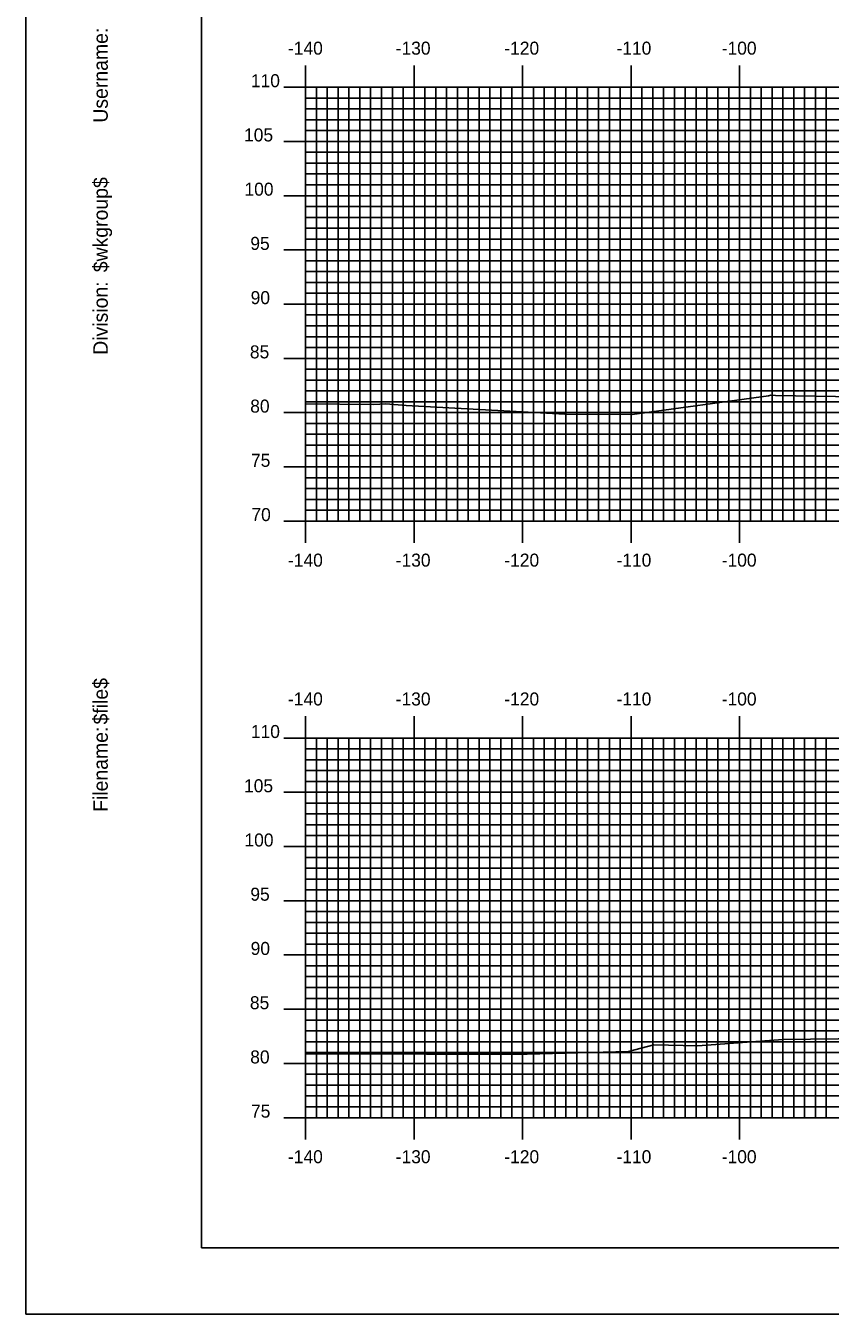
# Model space of a CAD drawing. Extents: x 852542 to 852886, y 364366 to 364586.
# Drawn here: x 852542.4 to 852616.5, y 364365.7 to 364484.5 of the extents above; entities that cross this region are included whole.
import ezdxf

# ---------------------------------------------------------------- set-up
doc = ezdxf.new("R2010")
doc.units = 0
for name, color, linetype in [('BORDER', 7, 'Continuous'), ('H_V ANNOTATION', 7, 'Continuous'), ('MAJOR', 7, 'Continuous'), ('MINOR', 7, 'Continuous'), ('PLOT BOUNDARY', 7, 'Continuous'), ('S_Roadway_Centerline', 7, 'Continuous')]:
    doc.layers.add(name, color=color, linetype=linetype)

msp = doc.modelspace()

# ---------------------------------------------------------------- linework, layer by layer
at = {"layer": 'BORDER'}
msp.add_lwpolyline([(852558.58, 364371.79), (852878.58, 364371.79), (852878.58, 364581.79), (852558.58, 364581.79)], close=True, dxfattribs=at)
at = {"layer": 'MAJOR'}
for p, q in [((852568.18, 364480.79), (852568.18, 364478.79)), ((852578.18, 364480.79), (852578.18, 364478.79)), ((852588.18, 364480.79), (852588.18, 364478.79)), ((852598.18, 364480.79), (852598.18, 364478.79)), ((852608.18, 364480.79), (852608.18, 364478.79)), ((852566.17, 364478.79), (852568.18, 364478.79)), ((852568.18, 364478.79), (852848.18, 364478.79)), ((852568.18, 364438.79), (852568.18, 364478.79)), ((852568.18, 364438.79), (852568.18, 364478.79)), ((852568.18, 364478.79), (852848.18, 364478.79)), ((852578.18, 364438.79), (852578.18, 364478.79)), ((852588.18, 364438.79), (852588.18, 364478.79)), ((852598.18, 364438.79), (852598.18, 364478.79)), ((852608.18, 364438.79), (852608.18, 364478.79)), ((852566.17, 364473.79), (852568.18, 364473.79)), ((852568.18, 364473.79), (852848.18, 364473.79)), ((852566.17, 364468.79), (852568.18, 364468.79)), ((852568.18, 364468.79), (852848.18, 364468.79)), ((852566.17, 364463.79), (852568.18, 364463.79)), ((852568.18, 364463.79), (852848.18, 364463.79)), ((852566.17, 364458.79), (852568.18, 364458.79)), ((852568.18, 364458.79), (852848.18, 364458.79)), ((852566.17, 364453.79), (852568.18, 364453.79)), ((852568.18, 364453.79), (852848.18, 364453.79)), ((852566.17, 364448.79), (852568.18, 364448.79)), ((852568.18, 364448.79), (852848.18, 364448.79)), ((852566.17, 364443.79), (852568.18, 364443.79)), ((852568.18, 364443.79), (852848.18, 364443.79)), ((852566.17, 364438.79), (852568.18, 364438.79)), ((852568.18, 364438.79), (852848.18, 364438.79)), ((852568.18, 364438.79), (852848.18, 364438.79)), ((852568.18, 364436.78), (852568.18, 364438.79)), ((852578.18, 364436.78), (852578.18, 364438.79)), ((852588.18, 364436.78), (852588.18, 364438.79)), ((852598.18, 364436.78), (852598.18, 364438.79)), ((852608.18, 364436.78), (852608.18, 364438.79)), ((852568.18, 364420.79), (852568.18, 364418.79)), ((852578.18, 364420.79), (852578.18, 364418.79)), ((852588.18, 364420.79), (852588.18, 364418.79)), ((852598.18, 364420.79), (852598.18, 364418.79)), ((852608.18, 364420.79), (852608.18, 364418.79)), ((852566.17, 364418.79), (852568.18, 364418.79)), ((852568.18, 364418.79), (852848.18, 364418.79)), ((852568.18, 364383.79), (852568.18, 364418.79)), ((852568.18, 364383.79), (852568.18, 364418.79)), ((852568.18, 364418.79), (852848.18, 364418.79)), ((852578.18, 364383.79), (852578.18, 364418.79)), ((852588.18, 364383.79), (852588.18, 364418.79)), ((852598.18, 364383.79), (852598.18, 364418.79)), ((852608.18, 364383.79), (852608.18, 364418.79)), ((852566.17, 364413.79), (852568.18, 364413.79)), ((852568.18, 364413.79), (852848.18, 364413.79)), ((852566.17, 364408.79), (852568.18, 364408.79)), ((852568.18, 364408.79), (852848.18, 364408.79)), ((852566.17, 364403.79), (852568.18, 364403.79)), ((852568.18, 364403.79), (852848.18, 364403.79)), ((852566.17, 364398.79), (852568.18, 364398.79)), ((852568.18, 364398.79), (852848.18, 364398.79)), ((852566.17, 364393.79), (852568.18, 364393.79)), ((852568.18, 364393.79), (852848.18, 364393.79)), ((852566.17, 364388.79), (852568.18, 364388.79)), ((852568.18, 364388.79), (852848.18, 364388.79)), ((852566.17, 364383.79), (852568.18, 364383.79)), ((852568.18, 364383.79), (852848.18, 364383.79)), ((852568.18, 364383.79), (852848.18, 364383.79)), ((852568.18, 364381.78), (852568.18, 364383.79)), ((852578.18, 364381.78), (852578.18, 364383.79)), ((852588.18, 364381.78), (852588.18, 364383.79)), ((852598.18, 364381.78), (852598.18, 364383.79)), ((852608.18, 364381.78), (852608.18, 364383.79))]:
    msp.add_line(p, q, dxfattribs=at)
at = {"layer": 'MINOR'}
for p, q in [((852569.18, 364438.79), (852569.18, 364478.79)), ((852570.18, 364438.79), (852570.18, 364478.79)), ((852571.18, 364438.79), (852571.18, 364478.79)), ((852572.18, 364438.79), (852572.18, 364478.79)), ((852573.18, 364438.79), (852573.18, 364478.79)), ((852574.18, 364438.79), (852574.18, 364478.79)), ((852575.18, 364438.79), (852575.18, 364478.79)), ((852576.18, 364438.79), (852576.18, 364478.79)), ((852577.18, 364438.79), (852577.18, 364478.79)), ((852579.18, 364438.79), (852579.18, 364478.79)), ((852580.18, 364438.79), (852580.18, 364478.79)), ((852581.18, 364438.79), (852581.18, 364478.79)), ((852582.18, 364438.79), (852582.18, 364478.79)), ((852583.18, 364438.79), (852583.18, 364478.79)), ((852584.18, 364438.79), (852584.18, 364478.79)), ((852585.18, 364438.79), (852585.18, 364478.79)), ((852586.18, 364438.79), (852586.18, 364478.79)), ((852587.18, 364438.79), (852587.18, 364478.79)), ((852589.18, 364438.79), (852589.18, 364478.79)), ((852590.18, 364438.79), (852590.18, 364478.79)), ((852591.18, 364438.79), (852591.18, 364478.79)), ((852592.18, 364438.79), (852592.18, 364478.79)), ((852593.18, 364438.79), (852593.18, 364478.79)), ((852594.18, 364438.79), (852594.18, 364478.79)), ((852595.18, 364438.79), (852595.18, 364478.79)), ((852596.18, 364438.79), (852596.18, 364478.79)), ((852597.18, 364438.79), (852597.18, 364478.79)), ((852599.18, 364438.79), (852599.18, 364478.79)), ((852600.18, 364438.79), (852600.18, 364478.79)), ((852601.18, 364438.79), (852601.18, 364478.79)), ((852602.18, 364438.79), (852602.18, 364478.79)), ((852603.18, 364438.79), (852603.18, 364478.79)), ((852604.18, 364438.79), (852604.18, 364478.79)), ((852605.18, 364438.79), (852605.18, 364478.79)), ((852606.18, 364438.79), (852606.18, 364478.79)), ((852607.18, 364438.79), (852607.18, 364478.79)), ((852609.18, 364438.79), (852609.18, 364478.79)), ((852610.18, 364438.79), (852610.18, 364478.79)), ((852611.18, 364438.79), (852611.18, 364478.79)), ((852612.18, 364438.79), (852612.18, 364478.79)), ((852613.18, 364438.79), (852613.18, 364478.79)), ((852614.18, 364438.79), (852614.18, 364478.79)), ((852615.18, 364438.79), (852615.18, 364478.79)), ((852616.18, 364438.79), (852616.18, 364478.79)), ((852568.18, 364477.79), (852848.18, 364477.79)), ((852568.18, 364477.79), (852570.18, 364477.79)), ((852568.18, 364476.79), (852848.18, 364476.79)), ((852568.18, 364476.79), (852570.18, 364476.79)), ((852568.18, 364475.79), (852848.18, 364475.79)), ((852568.18, 364475.79), (852570.18, 364475.79)), ((852568.18, 364474.79), (852848.18, 364474.79)), ((852568.18, 364474.79), (852570.18, 364474.79)), ((852568.18, 364472.79), (852848.18, 364472.79)), ((852568.18, 364472.79), (852570.18, 364472.79)), ((852568.18, 364471.79), (852848.18, 364471.79)), ((852568.18, 364471.79), (852570.18, 364471.79)), ((852568.18, 364470.79), (852848.18, 364470.79)), ((852568.18, 364470.79), (852570.18, 364470.79)), ((852568.18, 364469.79), (852848.18, 364469.79)), ((852568.18, 364469.79), (852570.18, 364469.79)), ((852568.18, 364467.79), (852848.18, 364467.79)), ((852568.18, 364467.79), (852570.18, 364467.79)), ((852568.18, 364466.79), (852848.18, 364466.79)), ((852568.18, 364466.79), (852570.18, 364466.79)), ((852568.18, 364465.79), (852848.18, 364465.79)), ((852568.18, 364465.79), (852570.18, 364465.79)), ((852568.18, 364464.79), (852848.18, 364464.79)), ((852568.18, 364464.79), (852570.18, 364464.79)), ((852568.18, 364462.79), (852848.18, 364462.79)), ((852568.18, 364462.79), (852570.18, 364462.79)), ((852568.18, 364461.79), (852848.18, 364461.79)), ((852568.18, 364461.79), (852570.18, 364461.79)), ((852568.18, 364460.79), (852848.18, 364460.79)), ((852568.18, 364460.79), (852570.18, 364460.79)), ((852568.18, 364459.79), (852848.18, 364459.79)), ((852568.18, 364459.79), (852570.18, 364459.79)), ((852568.18, 364457.79), (852848.18, 364457.79)), ((852568.18, 364457.79), (852570.18, 364457.79)), ((852568.18, 364456.79), (852848.18, 364456.79)), ((852568.18, 364456.79), (852570.18, 364456.79)), ((852568.18, 364455.79), (852848.18, 364455.79)), ((852568.18, 364455.79), (852570.18, 364455.79)), ((852568.18, 364454.79), (852848.18, 364454.79)), ((852568.18, 364454.79), (852570.18, 364454.79)), ((852568.18, 364452.79), (852848.18, 364452.79)), ((852568.18, 364452.79), (852570.18, 364452.79)), ((852568.18, 364451.79), (852848.18, 364451.79)), ((852568.18, 364451.79), (852570.18, 364451.79)), ((852568.18, 364450.79), (852848.18, 364450.79)), ((852568.18, 364450.79), (852570.18, 364450.79)), ((852568.18, 364449.79), (852848.18, 364449.79)), ((852568.18, 364449.79), (852570.18, 364449.79)), ((852568.18, 364447.79), (852848.18, 364447.79)), ((852568.18, 364447.79), (852570.18, 364447.79)), ((852568.18, 364446.79), (852848.18, 364446.79)), ((852568.18, 364446.79), (852570.18, 364446.79)), ((852568.18, 364445.79), (852848.18, 364445.79)), ((852568.18, 364445.79), (852570.18, 364445.79)), ((852568.18, 364444.79), (852848.18, 364444.79)), ((852568.18, 364444.79), (852570.18, 364444.79)), ((852568.18, 364442.79), (852848.18, 364442.79)), ((852568.18, 364442.79), (852570.18, 364442.79)), ((852568.18, 364441.79), (852848.18, 364441.79)), ((852568.18, 364441.79), (852570.18, 364441.79)), ((852568.18, 364440.79), (852848.18, 364440.79)), ((852568.18, 364440.79), (852570.18, 364440.79)), ((852568.18, 364439.79), (852848.18, 364439.79)), ((852568.18, 364439.79), (852570.18, 364439.79)), ((852568.18, 364417.79), (852848.18, 364417.79)), ((852568.18, 364417.79), (852570.18, 364417.79)), ((852569.18, 364383.79), (852569.18, 364418.79)), ((852570.18, 364383.79), (852570.18, 364418.79)), ((852571.18, 364383.79), (852571.18, 364418.79)), ((852572.18, 364383.79), (852572.18, 364418.79)), ((852573.18, 364383.79), (852573.18, 364418.79)), ((852574.18, 364383.79), (852574.18, 364418.79)), ((852575.18, 364383.79), (852575.18, 364418.79)), ((852576.18, 364383.79), (852576.18, 364418.79)), ((852577.18, 364383.79), (852577.18, 364418.79)), ((852579.18, 364383.79), (852579.18, 364418.79)), ((852580.18, 364383.79), (852580.18, 364418.79)), ((852581.18, 364383.79), (852581.18, 364418.79)), ((852582.18, 364383.79), (852582.18, 364418.79)), ((852583.18, 364383.79), (852583.18, 364418.79)), ((852584.18, 364383.79), (852584.18, 364418.79)), ((852585.18, 364383.79), (852585.18, 364418.79)), ((852586.18, 364383.79), (852586.18, 364418.79)), ((852587.18, 364383.79), (852587.18, 364418.79)), ((852589.18, 364383.79), (852589.18, 364418.79)), ((852590.18, 364383.79), (852590.18, 364418.79)), ((852591.18, 364383.79), (852591.18, 364418.79)), ((852592.18, 364383.79), (852592.18, 364418.79)), ((852593.18, 364383.79), (852593.18, 364418.79)), ((852594.18, 364383.79), (852594.18, 364418.79)), ((852595.18, 364383.79), (852595.18, 364418.79)), ((852596.18, 364383.79), (852596.18, 364418.79)), ((852597.18, 364383.79), (852597.18, 364418.79)), ((852599.18, 364383.79), (852599.18, 364418.79)), ((852600.18, 364383.79), (852600.18, 364418.79)), ((852601.18, 364383.79), (852601.18, 364418.79)), ((852602.18, 364383.79), (852602.18, 364418.79)), ((852603.18, 364383.79), (852603.18, 364418.79)), ((852604.18, 364383.79), (852604.18, 364418.79)), ((852605.18, 364383.79), (852605.18, 364418.79)), ((852606.18, 364383.79), (852606.18, 364418.79)), ((852607.18, 364383.79), (852607.18, 364418.79)), ((852609.18, 364383.79), (852609.18, 364418.79)), ((852610.18, 364383.79), (852610.18, 364418.79)), ((852611.18, 364383.79), (852611.18, 364418.79)), ((852612.18, 364383.79), (852612.18, 364418.79)), ((852613.18, 364383.79), (852613.18, 364418.79)), ((852614.18, 364383.79), (852614.18, 364418.79)), ((852615.18, 364383.79), (852615.18, 364418.79)), ((852616.18, 364383.79), (852616.18, 364418.79)), ((852568.18, 364416.79), (852848.18, 364416.79)), ((852568.18, 364416.79), (852570.18, 364416.79)), ((852568.18, 364415.79), (852848.18, 364415.79)), ((852568.18, 364415.79), (852570.18, 364415.79)), ((852568.18, 364414.79), (852848.18, 364414.79)), ((852568.18, 364414.79), (852570.18, 364414.79)), ((852568.18, 364412.79), (852848.18, 364412.79)), ((852568.18, 364412.79), (852570.18, 364412.79)), ((852568.18, 364411.79), (852848.18, 364411.79)), ((852568.18, 364411.79), (852570.18, 364411.79)), ((852568.18, 364410.79), (852848.18, 364410.79)), ((852568.18, 364410.79), (852570.18, 364410.79)), ((852568.18, 364409.79), (852848.18, 364409.79)), ((852568.18, 364409.79), (852570.18, 364409.79)), ((852568.18, 364407.79), (852848.18, 364407.79)), ((852568.18, 364407.79), (852570.18, 364407.79)), ((852568.18, 364406.79), (852848.18, 364406.79)), ((852568.18, 364406.79), (852570.18, 364406.79)), ((852568.18, 364405.79), (852848.18, 364405.79)), ((852568.18, 364405.79), (852570.18, 364405.79)), ((852568.18, 364404.79), (852848.18, 364404.79)), ((852568.18, 364404.79), (852570.18, 364404.79)), ((852568.18, 364402.79), (852848.18, 364402.79)), ((852568.18, 364402.79), (852570.18, 364402.79)), ((852568.18, 364401.79), (852848.18, 364401.79)), ((852568.18, 364401.79), (852570.18, 364401.79)), ((852568.18, 364400.79), (852848.18, 364400.79)), ((852568.18, 364400.79), (852570.18, 364400.79)), ((852568.18, 364399.79), (852848.18, 364399.79)), ((852568.18, 364399.79), (852570.18, 364399.79)), ((852568.18, 364397.79), (852848.18, 364397.79)), ((852568.18, 364397.79), (852570.18, 364397.79)), ((852568.18, 364396.79), (852848.18, 364396.79)), ((852568.18, 364396.79), (852570.18, 364396.79)), ((852568.18, 364395.79), (852848.18, 364395.79)), ((852568.18, 364395.79), (852570.18, 364395.79)), ((852568.18, 364394.79), (852848.18, 364394.79)), ((852568.18, 364394.79), (852570.18, 364394.79)), ((852568.18, 364392.79), (852848.18, 364392.79)), ((852568.18, 364392.79), (852570.18, 364392.79)), ((852568.18, 364391.79), (852848.18, 364391.79)), ((852568.18, 364391.79), (852570.18, 364391.79)), ((852568.18, 364390.79), (852848.18, 364390.79)), ((852568.18, 364390.79), (852570.18, 364390.79)), ((852568.18, 364389.79), (852848.18, 364389.79)), ((852568.18, 364389.79), (852570.18, 364389.79)), ((852568.18, 364387.79), (852848.18, 364387.79)), ((852568.18, 364387.79), (852570.18, 364387.79)), ((852568.18, 364386.79), (852848.18, 364386.79)), ((852568.18, 364386.79), (852570.18, 364386.79)), ((852568.18, 364385.79), (852848.18, 364385.79)), ((852568.18, 364385.79), (852570.18, 364385.79)), ((852568.18, 364384.79), (852848.18, 364384.79)), ((852568.18, 364384.79), (852570.18, 364384.79))]:
    msp.add_line(p, q, dxfattribs=at)
at = {"layer": 'PLOT BOUNDARY'}
msp.add_lwpolyline([(852542.39, 364365.67), (852882.39, 364365.67), (852882.39, 364585.67), (852542.39, 364585.67)], close=True, dxfattribs=at)
at = {"layer": 'S_Roadway_Centerline'}
for points in [[(852568.18, 364449.6), (852574.48, 364449.54), (852575.58, 364449.59), (852577.44, 364449.44), (852592.08, 364448.65), (852598.28, 364448.62), (852610.84, 364450.35), (852611.08, 364450.39), (852611.51, 364450.38), (852629.92, 364450.05), (852644.12, 364450.42), (852647.02, 364450.52), (852648.73, 364450.51), (852654.43, 364450.61), (852667.9, 364450.63), (852676.95, 364450.75), (852686.44, 364450.78), (852692.14, 364450.73)], [(852568.18, 364389.65), (852574.12, 364389.68), (852579.34, 364389.63), (852588.61, 364389.63), (852597.95, 364389.9), (852600.27, 364390.49), (852604.34, 364390.41), (852612.17, 364390.99), (852617.28, 364391.05), (852625.15, 364392.47), (852635.57, 364393.11), (852637.65, 364393.47), (852647.87, 364395.29), (852669.74, 364398.53), (852672.31, 364398.91), (852673.81, 364399.05), (852688.56, 364399.68), (852700.74, 364402.23)]]:
    msp.add_lwpolyline(points, dxfattribs=at)

# ---------------------------------------------------------------- texts
at = {"layer": 'BORDER'}
for s, p in [('Username:', (852549.95, 364475.52)), ('$wkgroup$', (852549.95, 364461.73)), ('Division:', (852549.95, 364454.12)), ('$file$', (852549.95, 364420.04)), ('Filename:', (852549.95, 364411.98))]:
    msp.add_text(s, height=1.339, rotation=90, dxfattribs=at).set_placement(p)
at = {"layer": 'H_V ANNOTATION'}
for s, p in [('-140', (852566.56, 364481.79)), ('-130', (852576.49, 364481.79)), ('-120', (852586.5, 364481.79)), ('-110', (852596.84, 364481.79)), ('-100', (852606.54, 364481.79)), ('110', (852563.14, 364478.79)), ('105', (852562.51, 364473.79)), ('100', (852562.55, 364468.79)), ('95', (852563.09, 364463.79)), ('90', (852563.12, 364458.79)), ('85', (852563.05, 364453.79)), ('80', (852563.08, 364448.79)), ('75', (852563.15, 364443.79)), ('70', (852563.19, 364438.79)), ('-140', (852566.56, 364434.59)), ('-130', (852576.49, 364434.59)), ('-120', (852586.5, 364434.59)), ('-110', (852596.84, 364434.59)), ('-100', (852606.54, 364434.59)), ('-140', (852566.56, 364421.79)), ('-130', (852576.49, 364421.79)), ('-120', (852586.5, 364421.79)), ('-110', (852596.84, 364421.79)), ('-100', (852606.54, 364421.79)), ('110', (852563.14, 364418.79)), ('105', (852562.51, 364413.79)), ('100', (852562.55, 364408.79)), ('95', (852563.09, 364403.79)), ('90', (852563.12, 364398.79)), ('85', (852563.05, 364393.79)), ('80', (852563.08, 364388.79)), ('75', (852563.15, 364383.79)), ('-140', (852566.56, 364379.59)), ('-130', (852576.49, 364379.59)), ('-120', (852586.5, 364379.59)), ('-110', (852596.84, 364379.59)), ('-100', (852606.54, 364379.59))]:
    msp.add_text(s, height=1.2, dxfattribs=at).set_placement(p)
at = {"layer": 'MAJOR'}
for p in [(852568.17, 364438.79), (852568.17, 364383.79)]:
    msp.add_text('-', height=0.012, dxfattribs=at).set_placement(p)

doc.saveas('drawing.dxf')
